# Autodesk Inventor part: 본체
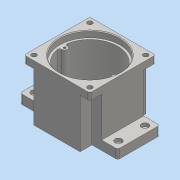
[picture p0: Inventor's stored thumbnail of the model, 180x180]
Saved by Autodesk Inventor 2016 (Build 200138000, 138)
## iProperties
Created: 2020-08
Part Number: 본체
Material: 일반
Document SubType Name: Modeling
Designer: User
Density: 1 g/cm^3
Appearance: 기본값
Author: User
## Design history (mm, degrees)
sketch "스케치1"
  geometry: L1 (33, 47)-(-33, 47); L2 (-33, 47)-(-33, -47); L3 (-33, -47)-(33, -47); L4 (33, -47)-(33, 47); L5 (33, 47)-(-33, -47); L6 (-33, 47)-(33, -47); L7 (-70, 30)-(70, 30); L8 (70, 30)-(70, -30); L9 (70, -30)-(-70, -30); L10 (-70, -30)-(-70, 30); L11 (-70, 30)-(70, -30); L12 (70, 30)-(-70, -30); 1 further point
  constraints: 24 end point, 4 midpoint, 4 parallel, 2 horizontal, 2 perpendicular
  dimensions: "d0" = 66 distance of L3.end L2.end; "d1" = 94 distance of L2.end L1.end; "d2" = 140 distance of L8.end L9.end; "d3" = 60 distance of L7.end L8.end
extrude "돌출1" new body sketch "스케치1" distance "d4" = 13; taper "d5" = 0 deg
sketch "스케치2"
  geometry: L1 (-47, 47)-(47, 47); L2 (47, 47)-(47, -47); L3 (47, -47)-(-47, -47); L4 (-47, -47)-(-47, 47); L5 (-47, 47)-(47, -47); L6 (47, 47)-(-47, -47); 1 further point
  constraints: 12 end point, 2 midpoint, 2 parallel, 1 horizontal, 1 perpendicular
  dimensions: "d6" = 94 distance of L2.end L3.end; "d7" = 94 distance of L1.end L2.end
extrude "돌출2" join sketch "스케치2" distance "d8" = 67; taper "d9" = 0 deg
sketch "스케치3"
  geometry: L1 (33, 30)-(47, 30) reference; L2 (47, 30)-(47, 47) reference; L3 (47, 47)-(33, 47) reference; L4 (33, 47)-(33, 30) reference; L5 (-47, 30)-(-33, 30) reference; L6 (-33, 30)-(-33, 47) reference; L7 (-33, 47)-(-47, 47) reference; L8 (-47, 47)-(-47, 30) reference; L9 (-33, -47)-(-33, -30) reference; L10 (-33, -30)-(-47, -30) reference; L11 (-47, -30)-(-47, -47) reference; L12 (-47, -47)-(-33, -47) reference; L13 (33, -30)-(33, -47) reference; L14 (33, -47)-(47, -47) reference; L15 (47, -47)-(47, -30) reference; L16 (47, -30)-(33, -30) reference; 1 further point
extrude "돌출3" cut sketch "스케치3" distance "d10" = 57; taper "d11" = 0 deg
sketch "스케치4"
  geometry: C1 r 27.5 at (0, 11); 1 further point
  constraints: 1 centre point, 1 vertical alignment
  dimensions: "d12" = 55 diameter of C1; "d13" = 11 distance of point (0, 0) C1.centre
extrude "돌출4" join sketch "스케치4" distance "d14" = 7; taper "d15" = 0 deg
sketch "스케치5"
  geometry: C1 r 43 at (0, 0); 1 further point
  constraints: 1 centre point, 1 coincident
  dimensions: "d16" = 86 diameter of C1
extrude "돌출5" cut sketch "스케치5" distance "d17" = 9; taper "d18" = 0 deg
sketch "스케치6"
  geometry: C1 r 40 at (0, 0); 1 further point
  constraints: 1 centre point, 1 coincident
  dimensions: "d19" = 80 diameter of C1
extrude "돌출6" cut sketch "스케치6" distance "d20" = 62; taper "d21" = 0 deg
sketch "스케치7"
  geometry: C1 r 27.5 at (0, 11) reference; C2 r 21 at (0, 11); C3 r 15 at (0, -20); 1 further point
  constraints: 2 centre point, 1 coincident, 1 vertical alignment
  dimensions: "d22" = 42 diameter of C2; "d23" = 30 diameter of C3; "d24" = 20 distance of C3.centre point (0, 0)
extrude "돌출7" join sketch "스케치7" distance "d25" = 7; taper "d26" = 0 deg
sketch "스케치8"
  geometry: C1 r 17.5 at (0, 11); A1 r 21 centre (0, 11) between (8.978, -7.984) and (-8.978, -7.984) reference; 1 further point
  constraints: 1 centre point, 1 coincident
  dimensions: "d27" = 35 diameter of C1
extrude "돌출8" cut sketch "스케치8" distance "d28" = 10; taper "d29" = 0 deg
sketch "스케치9"
  geometry: C1 r 11 at (0, -20); A1 r 15 centre (0, -20) between (-8.978, -7.984) and (8.978, -7.984) reference; 1 further point
  constraints: 1 centre point, 1 coincident
  dimensions: "d30" = 22 diameter of C1
extrude "돌출9" cut sketch "스케치9" distance "d31" = 7; taper "d32" = 0 deg
sketch "스케치10"
  geometry: C1 r 11 at (0, 0) reference; C2 r 9.5 at (0, 0); 1 further point
  constraints: 1 centre point, 1 coincident
  dimensions: "d33" = 19 diameter of C2
extrude "돌출10" cut sketch "스케치10" distance "d34" = 3; taper "d35" = 0 deg
sketch "스케치11"
  geometry: C1 r 27.5 at (0, 0) reference; C2 r 16 at (0, 0); 1 further point
  constraints: 1 centre point, 1 coincident
  dimensions: "d36" = 32 diameter of C2
extrude "돌출11" cut sketch "스케치11" distance "d37" = 8.3; taper "d38" = 0 deg
sketch "스케치12"
  geometry: C1 r 16 at (0, 0) reference; C2 r 12.5 at (0, 0); 1 further point
  constraints: 1 centre point, 1 coincident
  dimensions: "d39" = 25 diameter of C2
extrude "돌출12" cut sketch "스케치12" distance "d40" = 8; taper "d41" = 0 deg
sketch "스케치13"
  geometry: A1 r 4 centre (36, 0) between (36.19, 3.995) and (36.19, -3.995); A2 r 3 centre (36.333, 6.992) between (36.19, 3.995) and (39.279, 7.559); A3 r 3 centre (36.333, -6.992) between (39.279, -7.559) and (36.19, -3.995); A4 r 40 centre (0, 0) between (39.279, 7.559) and (39.279, -7.559) reference; 1 further point
  constraints: 8 point on circle, 5 tangent, 3 centre point, 1 horizontal alignment
  dimensions: "d42" = 8 diameter of A1; "d44" = 6 diameter of A2; "d45" = 6 diameter of A3
extrude "돌출13" join sketch "스케치13" stored distance "d46" = 8; taper "d47" = 0 deg
hole "구멍1" diameter "d50" = 3.242; stored, may be unused: countersink angle "d54" = 90 deg, drill point angle "d56" = 118 deg; dims "d48" = 10, "d49" = 10, "d51" = 7, "d52" = 4, "d53" = 2, "d55" = 9
sketch "스케치14"
  geometry: L1 (66, 0)-(0, 0) reference; L2 (80, -80)-(-14, -80) reference; 3 further points
  constraints: 1 midpoint, 1 vertical alignment, 1 other
  dimensions: "d57" = 40 distance from line of point (33, -40) L2
feature "엠보싱1" sketch "스케치14" dims "d0" = 66, "d1" = 94, "d58" = 0.5, "d59" = 0
sketch "스케치15"
  geometry: L1 (47, 47)-(-47, 47) reference; L2 (47, -47)-(47, 47) reference; C1 r 3.5 at (40, 40); 1 further point
  constraints: 1 centre point
  dimensions: "d60" = 7 diameter of C1; "d61" = 7 distance from line of L1 C1.centre; "d62" = 7 distance from line of C1.centre L2
extrude "돌출14" cut sketch "스케치15" distance "d63" = 20; taper "d64" = 0 deg
sketch "스케치16"
  geometry: L1 (-47, 30)-(-70, 30) reference; L2 (-70, 30)-(-70, -30) reference; C1 r 5 at (-60, 19); 1 further point
  constraints: 1 centre point
  dimensions: "d71" = 10 diameter of C1; "d72" = 11 distance from line of C1.centre L1; "d73" = 10 distance from line of C1.centre L2
extrude "돌출15" cut sketch "스케치16" distance "d74" = 5; taper "d75" = 0 deg
sketch "스케치17"
  geometry: C1 r 5 at (0, 0) reference; C2 r 2.25 at (0, 0); 1 further point
  constraints: 1 centre point, 1 coincident
  dimensions: "d76" = 4.5 diameter of C2
extrude "돌출16" cut sketch "스케치17" distance "d77" = 10; taper "d78" = 0 deg
fillet "모깎기1" dims "d85" = 3
fillet "모깎기2" dims "d86" = 3
chamfer "모따기1" distance "d87" = 1; stored, may be unused: second distance "d88" = 2, angle "d89" = 45 deg
chamfer "모따기2" distance "d90" = 0.8; stored, may be unused: second distance "d91" = 2, angle "d92" = 30 deg
node "솔리드1"
mirror "대칭1"
pattern_linear "직사각형 패턴1" dims "d67" = 80
pattern_linear "직사각형 패턴2" dims "d84" = 38
node "투영된 루프1"
node "투영된 루프2"
node "투영된 루프3"
node "투영된 루프4"
